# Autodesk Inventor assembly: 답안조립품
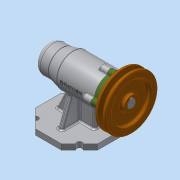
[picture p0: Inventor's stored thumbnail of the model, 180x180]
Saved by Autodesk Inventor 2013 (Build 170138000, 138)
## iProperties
Created: 2019-12
Part Number: 답안조립품
Document SubType Name: Assembly
Designer: Administrator
Author: Administrator
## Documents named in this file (12)
- C:\Users\Administrator\Desktop\491204V1021\답안조립품.iam
- C:\Users\Administrator\Desktop\491204V1021\1-본체.ipt
- C:\Users\Administrator\Desktop\491204V1021\커버.ipt
- C:\Users\Administrator\Desktop\491204V1021\축.ipt
- C:\Users\Administrator\Desktop\491204V1021\베어링 6004.ipt
- C:\Users\Administrator\Desktop\491204V1021\어댑터슬리브.ipt
- C:\Users\Administrator\Desktop\491204V1021\베어링 51202.ipt
- C:\Users\Administrator\Desktop\491204V1021\볼트 M4.ipt
- C:\Users\Administrator\Desktop\491204V1021\오일 실.ipt
- C:\Users\Administrator\Desktop\491204V1021\키 5 x 5 x 16.ipt
- C:\Users\Administrator\Desktop\491204V1021\V벨트풀리.ipt
- C:\Users\Administrator\Desktop\491204V1021\멈춤나사 M3.ipt
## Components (2 placed, 2 different names)
1. 1-본체:1
2. V벨트풀리:1 — 각도:3
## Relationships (1: Angle 1)
- 각도:3 [Angle]: V벨트풀리:1
